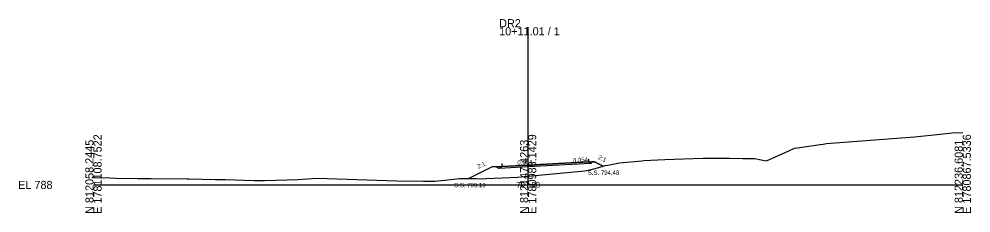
# Model space of a CAD drawing. Extents: x -26 to 303, y -10 to 2560.
# Drawn here: x -25.7 to 302.8, y 490.3 to 557.3 of the extents above; entities that cross this region are included whole.
import ezdxf

# ---------------------------------------------------------------- set-up
doc = ezdxf.new("R2010")
doc.units = 0
for name, color, linetype in [('Exist Cross Section Cell', 7, 'Continuous'), ('Exist XS Center Line Elevation Label', 7, 'Continuous'), ('Exist XS Ground Line', 7, 'Continuous'), ('Prop XS Dump Level', 7, 'Continuous'), ('Prop XS Earthwork Shape', 7, 'Continuous'), ('Prop XS EOT Tick Mark', 7, 'Continuous'), ('Prop XS Finish Grade', 7, 'Continuous'), ('Prop XS Finish Grade Earthwork', 7, 'Continuous'), ('Prop XS Finish Grade Pavement', 7, 'Continuous'), ('Prop XS Pvmt Edge Slope', 7, 'Continuous'), ('Prop XS SE Text', 7, 'Continuous'), ('Prop XS Side Slope Text', 7, 'Continuous'), ('Prop XS SS Elevation Text', 7, 'Continuous'), ('Prop XS Subgrade Earthwork', 7, 'Continuous')]:
    doc.layers.add(name, color=color, linetype=linetype)

msp = doc.modelspace()

# ---------------------------------------------------------------- linework, layer by layer
at = {"layer": 'Exist Cross Section Cell'}
for p, q in [((150, 500), (150, 554.45)), ((0, 500), (150, 500)), ((150, 500), (300, 500))]:
    msp.add_line(p, q, dxfattribs=at)
at = {"layer": 'Exist XS Ground Line'}
for p, q in [((252.95, 514.25), (283.34, 516.63)), ((283.34, 516.63), (292.21, 517.53)), ((292.21, 517.53), (296.31, 517.98)), ((296.31, 517.98), (300, 518.15)), ((239.94, 511.8), (241.95, 512.68)), ((241.95, 512.68), (243.01, 512.86)), ((243.01, 512.86), (250.75, 513.93)), ((250.75, 513.93), (251.8, 514.13)), ((251.8, 514.13), (252.95, 514.25)), ((203.6, 509.02), (210.44, 509.23)), ((210.44, 509.23), (219.54, 509.19)), ((232.27, 508.36), (239.94, 511.8)), ((172.28, 505.41), (174.4, 505.99)), ((174.4, 505.99), (176.64, 506.76)), ((176.64, 506.76), (177.46, 506.82)), ((177.46, 506.82), (181.52, 507.58)), ((181.52, 507.58), (189.21, 508.35)), ((189.21, 508.35), (189.96, 508.47)), ((189.96, 508.47), (197.23, 508.82)), ((197.23, 508.82), (203.6, 509.02)), ((219.54, 509.19), (223.98, 509.13)), ((223.98, 509.13), (226.2, 509.07)), ((226.2, 509.07), (228.25, 509.07)), ((228.25, 509.07), (230.48, 508.69)), ((230.48, 508.69), (232.27, 508.36)), ((146.3, 502.64), (150, 503)), ((150, 503), (169.52, 504.88)), ((169.52, 504.88), (172.28, 505.41)), ((0, 502.57), (5.66, 502.42)), ((5.66, 502.42), (7.61, 502.33)), ((7.61, 502.33), (15.36, 502.24)), ((15.36, 502.24), (18.73, 502.2)), ((18.73, 502.2), (19.91, 502.18)), ((19.91, 502.18), (32.27, 502.07)), ((32.27, 502.07), (33.03, 502.06)), ((33.03, 502.06), (41.98, 501.84)), ((41.98, 501.84), (45.61, 501.86)), ((45.61, 501.86), (55.42, 501.5)), ((55.42, 501.5), (57.86, 501.47)), ((57.86, 501.47), (59.05, 501.53)), ((59.05, 501.53), (62.94, 501.66)), ((62.94, 501.66), (70.56, 501.92)), ((70.56, 501.92), (77.19, 502.34)), ((77.19, 502.34), (104.74, 501.38)), ((104.74, 501.38), (113.9, 501.3)), ((113.9, 501.3), (117.79, 501.31)), ((117.79, 501.31), (121.24, 501.62)), ((121.24, 501.62), (126.33, 502.22)), ((126.33, 502.22), (132.11, 502.16)), ((132.11, 502.16), (132.95, 502.15)), ((132.95, 502.15), (146.3, 502.64))]:
    msp.add_line(p, q, dxfattribs=at)
at = {"layer": 'Prop XS Dump Level'}
for p, q in [((150, 506.82), (141.06, 506.35)), ((170.95, 507.94), (150, 506.82))]:
    msp.add_line(p, q, dxfattribs=at)
at = {"layer": 'Prop XS Earthwork Shape'}
msp.add_lwpolyline([(129.54, 502.19), (132.11, 502.16), (132.95, 502.15), (146.3, 502.64), (150, 503), (169.52, 504.88), (172.28, 505.41), (174.4, 505.99), (175.85, 506.48), (172.95, 507.93), (172.05, 507.94), (171.5, 507.39), (150.03, 506.24), (139.92, 505.7), (138.95, 506.25), (137.54, 506.19)], close=True, dxfattribs=at)
at = {"layer": 'Prop XS EOT Tick Mark'}
for p, q in [((141.06, 506.35), (141.06, 507.35)), ((170.95, 507.94), (170.95, 508.94))]:
    msp.add_line(p, q, dxfattribs=at)
at = {"layer": 'Prop XS Finish Grade'}
for p, q in [((141.06, 506.35), (138.95, 506.25)), ((170.95, 507.94), (172.05, 507.94))]:
    msp.add_line(p, q, dxfattribs=at)
at = {"layer": 'Prop XS Finish Grade Earthwork'}
for p, q in [((137.54, 506.19), (129.54, 502.19)), ((138.95, 506.25), (137.54, 506.19)), ((172.05, 507.94), (172.95, 507.93)), ((172.95, 507.93), (175.85, 506.48))]:
    msp.add_line(p, q, dxfattribs=at)
at = {"layer": 'Prop XS Finish Grade Pavement'}
for p, q in [((141.06, 506.35), (150, 506.82)), ((150, 506.82), (170.95, 507.94))]:
    msp.add_line(p, q, dxfattribs=at)
at = {"layer": 'Prop XS Pvmt Edge Slope'}
for p, q in [((141.06, 506.35), (139.92, 505.7)), ((170.95, 507.94), (171.5, 507.39))]:
    msp.add_line(p, q, dxfattribs=at)
at = {"layer": 'Prop XS Subgrade Earthwork'}
for p, q in [((139.92, 505.7), (138.95, 506.25)), ((150.03, 506.24), (139.92, 505.7)), ((171.5, 507.39), (150.03, 506.24)), ((171.5, 507.39), (172.05, 507.94))]:
    msp.add_line(p, q, dxfattribs=at)

# ---------------------------------------------------------------- texts
at = {"layer": 'Exist Cross Section Cell'}
for s, p in [('DR2', (140, 554.45)), ('10+11.01 / 1', (140, 551.65)), ('EL 788', (-26, 498.6))]:
    msp.add_text(s, height=2.8, dxfattribs=at).set_placement(p)
for s, p in [('E 1781108.7522', (2.8, 490)), ('E 1780988.1429', (152.8, 490)), ('E 1780867.5336', (302.8, 490)), ('N 812058.2445', (0, 490)), ('N 812147.4263', (150, 490)), ('N 812236.6081', (300, 490))]:
    msp.add_text(s, height=2.8, rotation=90, dxfattribs=at).set_placement(p)
at = {"layer": 'Exist XS Center Line Elevation Label'}
msp.add_text('791.00', height=2, dxfattribs=at).set_placement((145.95, 499))
at = {"layer": 'Prop XS Dump Level'}
for p in [(137.54, 506.15), (172.95, 507.89)]:
    msp.add_text('Case1', height=0.04, dxfattribs=at).set_placement(p)
at = {"layer": 'Prop XS SE Text'}
for p in [(165.51, 507.74), (146.32, 506.95)]:
    msp.add_text('0.054', height=1.5, rotation=3.0624, dxfattribs=at).set_placement(p)
at = {"layer": 'Prop XS Side Slope Text'}
for rotation, p in [(333.4349, (173.98, 509.09)), (26.5651, (132.87, 505.53))]:
    msp.add_text('2:1', height=1.5, rotation=rotation, dxfattribs=at).set_placement(p)
at = {"layer": 'Prop XS SS Elevation Text'}
for s, p in [('S.S. 794.48', (170.62, 503.48)), ('S.S. 790.19', (124.5, 499.19))]:
    msp.add_text(s, height=1.5, dxfattribs=at).set_placement(p)

doc.saveas('drawing.dxf')
